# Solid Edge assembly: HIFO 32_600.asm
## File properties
Title: Zylinder
Author: ahadarics
Template: iso assembly.asm
Last saved by: ahadarics
Revision: 64
Application: Solid Edge
Username: ahadarics
Dokumentum tartalom típus: 1
Document Number: HIFO 32/600
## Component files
Profilrohr 32_600.par
Kit_1.par
Mutter.par
Kit_2.par
Kolbenstange 32_600.par
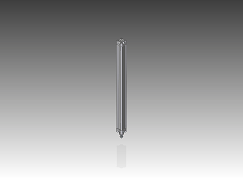
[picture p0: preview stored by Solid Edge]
